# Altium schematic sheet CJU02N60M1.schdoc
size 127 x 101 mm
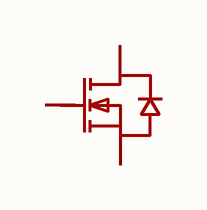
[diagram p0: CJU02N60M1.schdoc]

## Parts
Q?  cju02n60m1  [TO-252-2_L6.6-W6.1-P4.58-LS9.9-BR]  (value not drawn)

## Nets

Not connected (* = marked no-connect by the designer): Q? 1(G) 2(D) 3(S)

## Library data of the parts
Q? = cju02n60m1: 数量:1个N沟道;漏源电压(Vdss):600V;连续漏极电流(Id):2A;导通电阻(RDS(on)):3.7Ω@10V;耗散功率(Pd):31W;阈值电压(Vgs(th)):4V;; Manufacturer: CJ(江苏长电/长晶); AddInBom: yes; ModelId: ce57f84d66384067af8a68020b6de06d; ModelName: TO-252-2L-3P_L6.6-W6.1-H2.3-LS10.1-P4.6; ModelTransform: 259.842,390.52442,0,90,0,0,-39.375,0,0; Number: 1个N沟道; Drain to Source Voltage: 600V; Current - Continuous Drain(Id): 2A; Pd - Power Dissipation: 31W; Gate Threshold Voltage (Vgs(th)): 4V; Gate Charge(Qg): 60nC@10V; Input Capacitance(Ciss): 322pF; Reverse Transfer Capacitance (Crss@Vds): 7pF; Type: N沟道; Output Capacitance(Coss): 38pF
